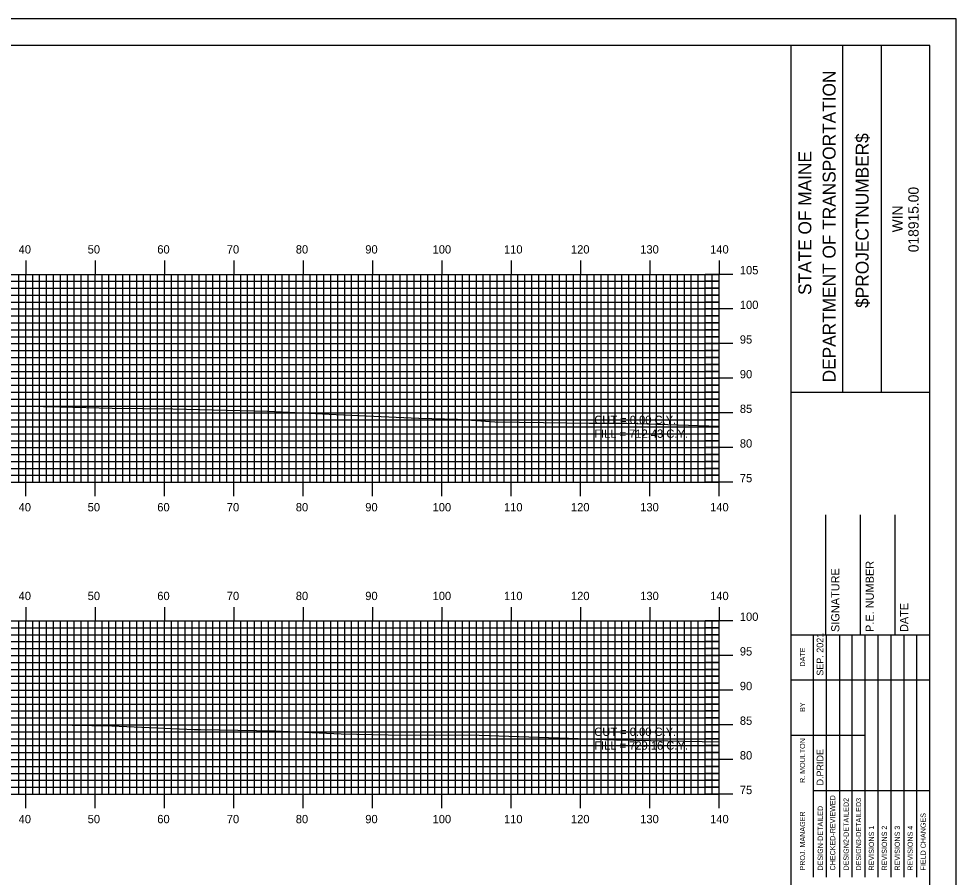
# Model space of a CAD drawing. Extents: x 854116 to 854460, y 364366 to 364586.
# Drawn here: x 854321.2 to 854456.4, y 364461.8 to 364585.7 of the extents above; entities that cross this region are included whole.
import ezdxf

# ---------------------------------------------------------------- set-up
doc = ezdxf.new("R2010")
doc.units = 0
for name, color, linetype in [('BORDER', 7, 'Continuous'), ('D_Text_Standard', 7, 'Continuous'), ('H_V ANNOTATION', 7, 'Continuous'), ('MAJOR', 7, 'Continuous'), ('MINOR', 7, 'Continuous'), ('PLOT BOUNDARY', 7, 'Continuous'), ('S_Roadway_Centerline', 7, 'Continuous')]:
    doc.layers.add(name, color=color, linetype=linetype)

msp = doc.modelspace()

# ---------------------------------------------------------------- linework, layer by layer
at = {"layer": 'BORDER'}
for p, q in [((854432.63, 364371.79), (854432.63, 364581.79)), ((854440.09, 364531.78), (854440.09, 364581.78)), ((854445.68, 364531.78), (854445.68, 364581.78)), ((854432.63, 364531.78), (854452.63, 364531.78)), ((854437.63, 364496.79), (854437.63, 364514.09)), ((854442.63, 364496.79), (854442.63, 364514.09)), ((854447.63, 364496.79), (854447.63, 364514.09)), ((854432.63, 364496.79), (854452.63, 364496.79))]:
    msp.add_line(p, q, dxfattribs=at)
msp.add_lwpolyline([(854132.63, 364371.79), (854452.63, 364371.79), (854452.63, 364581.79), (854132.63, 364581.79)], close=True, dxfattribs=at)
for points in [[(854435.86, 364490.29), (854435.86, 364496.79)], [(854437.73, 364461.8), (854437.73, 364496.79)], [(854439.59, 364496.79), (854439.59, 364461.8)], [(854441.45, 364461.8), (854441.45, 364496.79)], [(854443.32, 364461.8), (854443.32, 364496.79)], [(854445.18, 364461.8), (854445.18, 364496.79)], [(854447.04, 364461.8), (854447.04, 364496.79)], [(854448.91, 364461.8), (854448.91, 364496.79)], [(854450.77, 364461.8), (854450.77, 364496.79)], [(854435.86, 364461.8), (854435.86, 364495.38)], [(854432.63, 364490.29), (854452.63, 364490.29)], [(854432.63, 364482.29), (854435.86, 364482.29)], [(854435.86, 364482.29), (854443.31, 364482.29)], [(854435.86, 364474.29), (854452.63, 364474.29)]]:
    msp.add_lwpolyline(points, dxfattribs=at)
at = {"layer": 'MAJOR'}
for p, q in [((854322.23, 364550.79), (854322.23, 364548.79)), ((854332.23, 364550.79), (854332.23, 364548.79)), ((854342.23, 364550.79), (854342.23, 364548.79)), ((854352.23, 364550.79), (854352.23, 364548.79)), ((854362.23, 364550.79), (854362.23, 364548.79)), ((854372.23, 364550.79), (854372.23, 364548.79)), ((854382.23, 364550.79), (854382.23, 364548.79)), ((854392.23, 364550.79), (854392.23, 364548.79)), ((854402.23, 364550.79), (854402.23, 364548.79)), ((854412.23, 364550.79), (854412.23, 364548.79)), ((854422.23, 364550.79), (854422.23, 364548.79)), ((854142.23, 364548.79), (854422.23, 364548.79)), ((854142.23, 364548.79), (854422.23, 364548.79)), ((854322.23, 364518.79), (854322.23, 364548.79)), ((854332.23, 364518.79), (854332.23, 364548.79)), ((854342.23, 364518.79), (854342.23, 364548.79)), ((854352.23, 364518.79), (854352.23, 364548.79)), ((854362.23, 364518.79), (854362.23, 364548.79)), ((854372.23, 364518.79), (854372.23, 364548.79)), ((854382.23, 364518.79), (854382.23, 364548.79)), ((854392.23, 364518.79), (854392.23, 364548.79)), ((854402.23, 364518.79), (854402.23, 364548.79)), ((854412.23, 364518.79), (854412.23, 364548.79)), ((854424.23, 364548.79), (854420.23, 364548.79)), ((854422.23, 364518.79), (854422.23, 364548.79)), ((854422.23, 364518.79), (854422.23, 364548.79)), ((854142.23, 364543.79), (854422.23, 364543.79)), ((854424.23, 364543.79), (854420.23, 364543.79)), ((854142.23, 364538.79), (854422.23, 364538.79)), ((854424.23, 364538.79), (854420.23, 364538.79)), ((854142.23, 364533.79), (854422.23, 364533.79)), ((854424.23, 364533.79), (854420.23, 364533.79)), ((854142.23, 364528.79), (854422.23, 364528.79)), ((854424.23, 364528.79), (854420.23, 364528.79)), ((854142.23, 364523.79), (854422.23, 364523.79)), ((854424.23, 364523.79), (854420.23, 364523.79)), ((854142.23, 364518.79), (854422.23, 364518.79)), ((854142.23, 364518.79), (854422.23, 364518.79)), ((854322.23, 364516.78), (854322.23, 364518.79)), ((854332.23, 364516.78), (854332.23, 364518.79)), ((854342.23, 364516.78), (854342.23, 364518.79)), ((854352.23, 364516.78), (854352.23, 364518.79)), ((854362.23, 364516.78), (854362.23, 364518.79)), ((854372.23, 364516.78), (854372.23, 364518.79)), ((854382.23, 364516.78), (854382.23, 364518.79)), ((854392.23, 364516.78), (854392.23, 364518.79)), ((854402.23, 364516.78), (854402.23, 364518.79)), ((854412.23, 364516.78), (854412.23, 364518.79)), ((854424.23, 364518.79), (854420.23, 364518.79)), ((854422.23, 364516.78), (854422.23, 364518.79)), ((854322.23, 364500.79), (854322.23, 364498.79)), ((854332.23, 364500.79), (854332.23, 364498.79)), ((854342.23, 364500.79), (854342.23, 364498.79)), ((854352.23, 364500.79), (854352.23, 364498.79)), ((854362.23, 364500.79), (854362.23, 364498.79)), ((854372.23, 364500.79), (854372.23, 364498.79)), ((854382.23, 364500.79), (854382.23, 364498.79)), ((854392.23, 364500.79), (854392.23, 364498.79)), ((854402.23, 364500.79), (854402.23, 364498.79)), ((854412.23, 364500.79), (854412.23, 364498.79)), ((854422.23, 364500.79), (854422.23, 364498.79)), ((854142.23, 364498.79), (854422.23, 364498.79)), ((854142.23, 364498.79), (854422.23, 364498.79)), ((854322.23, 364473.79), (854322.23, 364498.79)), ((854332.23, 364473.79), (854332.23, 364498.79)), ((854342.23, 364473.79), (854342.23, 364498.79)), ((854352.23, 364473.79), (854352.23, 364498.79)), ((854362.23, 364473.79), (854362.23, 364498.79)), ((854372.23, 364473.79), (854372.23, 364498.79)), ((854382.23, 364473.79), (854382.23, 364498.79)), ((854392.23, 364473.79), (854392.23, 364498.79)), ((854402.23, 364473.79), (854402.23, 364498.79)), ((854412.23, 364473.79), (854412.23, 364498.79)), ((854424.23, 364498.79), (854420.23, 364498.79)), ((854422.23, 364473.79), (854422.23, 364498.79)), ((854422.23, 364473.79), (854422.23, 364498.79)), ((854142.23, 364493.79), (854422.23, 364493.79)), ((854424.23, 364493.79), (854420.23, 364493.79)), ((854142.23, 364488.79), (854422.23, 364488.79)), ((854424.23, 364488.79), (854420.23, 364488.79)), ((854142.23, 364483.79), (854422.23, 364483.79)), ((854424.23, 364483.79), (854420.23, 364483.79)), ((854142.23, 364478.79), (854422.23, 364478.79)), ((854424.23, 364478.79), (854420.23, 364478.79)), ((854142.23, 364473.79), (854422.23, 364473.79)), ((854142.23, 364473.79), (854422.23, 364473.79)), ((854322.23, 364471.78), (854322.23, 364473.79)), ((854332.23, 364471.78), (854332.23, 364473.79)), ((854342.23, 364471.78), (854342.23, 364473.79)), ((854352.23, 364471.78), (854352.23, 364473.79)), ((854362.23, 364471.78), (854362.23, 364473.79)), ((854372.23, 364471.78), (854372.23, 364473.79)), ((854382.23, 364471.78), (854382.23, 364473.79)), ((854392.23, 364471.78), (854392.23, 364473.79)), ((854402.23, 364471.78), (854402.23, 364473.79)), ((854412.23, 364471.78), (854412.23, 364473.79)), ((854424.23, 364473.79), (854420.23, 364473.79)), ((854422.23, 364471.78), (854422.23, 364473.79))]:
    msp.add_line(p, q, dxfattribs=at)
at = {"layer": 'MINOR'}
for p, q in [((854142.23, 364547.79), (854422.23, 364547.79)), ((854321.23, 364518.79), (854321.23, 364548.79)), ((854323.23, 364518.79), (854323.23, 364548.79)), ((854324.23, 364518.79), (854324.23, 364548.79)), ((854325.23, 364518.79), (854325.23, 364548.79)), ((854326.23, 364518.79), (854326.23, 364548.79)), ((854327.23, 364518.79), (854327.23, 364548.79)), ((854328.23, 364518.79), (854328.23, 364548.79)), ((854329.23, 364518.79), (854329.23, 364548.79)), ((854330.23, 364518.79), (854330.23, 364548.79)), ((854331.23, 364518.79), (854331.23, 364548.79)), ((854333.23, 364518.79), (854333.23, 364548.79)), ((854334.23, 364518.79), (854334.23, 364548.79)), ((854335.23, 364518.79), (854335.23, 364548.79)), ((854336.23, 364518.79), (854336.23, 364548.79)), ((854337.23, 364518.79), (854337.23, 364548.79)), ((854338.23, 364518.79), (854338.23, 364548.79)), ((854339.23, 364518.79), (854339.23, 364548.79)), ((854340.23, 364518.79), (854340.23, 364548.79)), ((854341.23, 364518.79), (854341.23, 364548.79)), ((854343.23, 364518.79), (854343.23, 364548.79)), ((854344.23, 364518.79), (854344.23, 364548.79)), ((854345.23, 364518.79), (854345.23, 364548.79)), ((854346.23, 364518.79), (854346.23, 364548.79)), ((854347.23, 364518.79), (854347.23, 364548.79)), ((854348.23, 364518.79), (854348.23, 364548.79)), ((854349.23, 364518.79), (854349.23, 364548.79)), ((854350.23, 364518.79), (854350.23, 364548.79)), ((854351.23, 364518.79), (854351.23, 364548.79)), ((854353.23, 364518.79), (854353.23, 364548.79)), ((854354.23, 364518.79), (854354.23, 364548.79)), ((854355.23, 364518.79), (854355.23, 364548.79)), ((854356.23, 364518.79), (854356.23, 364548.79)), ((854357.23, 364518.79), (854357.23, 364548.79)), ((854358.23, 364518.79), (854358.23, 364548.79)), ((854359.23, 364518.79), (854359.23, 364548.79)), ((854360.23, 364518.79), (854360.23, 364548.79)), ((854361.23, 364518.79), (854361.23, 364548.79)), ((854363.23, 364518.79), (854363.23, 364548.79)), ((854364.23, 364518.79), (854364.23, 364548.79)), ((854365.23, 364518.79), (854365.23, 364548.79)), ((854366.23, 364518.79), (854366.23, 364548.79)), ((854367.23, 364518.79), (854367.23, 364548.79)), ((854368.23, 364518.79), (854368.23, 364548.79)), ((854369.23, 364518.79), (854369.23, 364548.79)), ((854370.23, 364518.79), (854370.23, 364548.79)), ((854371.23, 364518.79), (854371.23, 364548.79)), ((854373.23, 364518.79), (854373.23, 364548.79)), ((854374.23, 364518.79), (854374.23, 364548.79)), ((854375.23, 364518.79), (854375.23, 364548.79)), ((854376.23, 364518.79), (854376.23, 364548.79)), ((854377.23, 364518.79), (854377.23, 364548.79)), ((854378.23, 364518.79), (854378.23, 364548.79)), ((854379.23, 364518.79), (854379.23, 364548.79)), ((854380.23, 364518.79), (854380.23, 364548.79)), ((854381.23, 364518.79), (854381.23, 364548.79)), ((854383.23, 364518.79), (854383.23, 364548.79)), ((854384.23, 364518.79), (854384.23, 364548.79)), ((854385.23, 364518.79), (854385.23, 364548.79)), ((854386.23, 364518.79), (854386.23, 364548.79)), ((854387.23, 364518.79), (854387.23, 364548.79)), ((854388.23, 364518.79), (854388.23, 364548.79)), ((854389.23, 364518.79), (854389.23, 364548.79)), ((854390.23, 364518.79), (854390.23, 364548.79)), ((854391.23, 364518.79), (854391.23, 364548.79)), ((854393.23, 364518.79), (854393.23, 364548.79)), ((854394.23, 364518.79), (854394.23, 364548.79)), ((854395.23, 364518.79), (854395.23, 364548.79)), ((854396.23, 364518.79), (854396.23, 364548.79)), ((854397.23, 364518.79), (854397.23, 364548.79)), ((854398.23, 364518.79), (854398.23, 364548.79)), ((854399.23, 364518.79), (854399.23, 364548.79)), ((854400.23, 364518.79), (854400.23, 364548.79)), ((854401.23, 364518.79), (854401.23, 364548.79)), ((854403.23, 364518.79), (854403.23, 364548.79)), ((854404.23, 364518.79), (854404.23, 364548.79)), ((854405.23, 364518.79), (854405.23, 364548.79)), ((854406.23, 364518.79), (854406.23, 364548.79)), ((854407.23, 364518.79), (854407.23, 364548.79)), ((854408.23, 364518.79), (854408.23, 364548.79)), ((854409.23, 364518.79), (854409.23, 364548.79)), ((854410.23, 364518.79), (854410.23, 364548.79)), ((854411.23, 364518.79), (854411.23, 364548.79)), ((854413.23, 364518.79), (854413.23, 364548.79)), ((854414.23, 364518.79), (854414.23, 364548.79)), ((854415.23, 364518.79), (854415.23, 364548.79)), ((854416.23, 364518.79), (854416.23, 364548.79)), ((854417.23, 364518.79), (854417.23, 364548.79)), ((854418.23, 364518.79), (854418.23, 364548.79)), ((854419.23, 364518.79), (854419.23, 364548.79)), ((854420.23, 364518.79), (854420.23, 364548.79)), ((854422.23, 364547.79), (854420.23, 364547.79)), ((854421.23, 364518.79), (854421.23, 364548.79)), ((854142.23, 364546.79), (854422.23, 364546.79)), ((854422.23, 364546.79), (854420.23, 364546.79)), ((854142.23, 364545.79), (854422.23, 364545.79)), ((854422.23, 364545.79), (854420.23, 364545.79)), ((854142.23, 364544.79), (854422.23, 364544.79)), ((854422.23, 364544.79), (854420.23, 364544.79)), ((854142.23, 364542.79), (854422.23, 364542.79)), ((854422.23, 364542.79), (854420.23, 364542.79)), ((854142.23, 364541.79), (854422.23, 364541.79)), ((854422.23, 364541.79), (854420.23, 364541.79)), ((854142.23, 364540.79), (854422.23, 364540.79)), ((854142.23, 364539.79), (854422.23, 364539.79)), ((854422.23, 364540.79), (854420.23, 364540.79)), ((854422.23, 364539.79), (854420.23, 364539.79)), ((854142.23, 364537.79), (854422.23, 364537.79)), ((854422.23, 364537.79), (854420.23, 364537.79)), ((854142.23, 364536.79), (854422.23, 364536.79)), ((854142.23, 364535.79), (854422.23, 364535.79)), ((854422.23, 364536.79), (854420.23, 364536.79)), ((854422.23, 364535.79), (854420.23, 364535.79)), ((854142.23, 364534.79), (854422.23, 364534.79)), ((854422.23, 364534.79), (854420.23, 364534.79)), ((854142.23, 364532.79), (854422.23, 364532.79)), ((854422.23, 364532.79), (854420.23, 364532.79)), ((854142.23, 364531.79), (854422.23, 364531.79)), ((854422.23, 364531.79), (854420.23, 364531.79)), ((854142.23, 364530.79), (854422.23, 364530.79)), ((854422.23, 364530.79), (854420.23, 364530.79)), ((854142.23, 364529.79), (854422.23, 364529.79)), ((854422.23, 364529.79), (854420.23, 364529.79)), ((854142.23, 364527.79), (854422.23, 364527.79)), ((854422.23, 364527.79), (854420.23, 364527.79)), ((854142.23, 364526.79), (854422.23, 364526.79)), ((854422.23, 364526.79), (854420.23, 364526.79)), ((854142.23, 364525.79), (854422.23, 364525.79)), ((854142.23, 364524.79), (854422.23, 364524.79)), ((854422.23, 364525.79), (854420.23, 364525.79)), ((854422.23, 364524.79), (854420.23, 364524.79)), ((854142.23, 364522.79), (854422.23, 364522.79)), ((854422.23, 364522.79), (854420.23, 364522.79)), ((854142.23, 364521.79), (854422.23, 364521.79)), ((854142.23, 364520.79), (854422.23, 364520.79)), ((854422.23, 364521.79), (854420.23, 364521.79)), ((854422.23, 364520.79), (854420.23, 364520.79)), ((854142.23, 364519.79), (854422.23, 364519.79)), ((854422.23, 364519.79), (854420.23, 364519.79)), ((854142.23, 364497.79), (854422.23, 364497.79)), ((854321.23, 364473.79), (854321.23, 364498.79)), ((854323.23, 364473.79), (854323.23, 364498.79)), ((854324.23, 364473.79), (854324.23, 364498.79)), ((854325.23, 364473.79), (854325.23, 364498.79)), ((854326.23, 364473.79), (854326.23, 364498.79)), ((854327.23, 364473.79), (854327.23, 364498.79)), ((854328.23, 364473.79), (854328.23, 364498.79)), ((854329.23, 364473.79), (854329.23, 364498.79)), ((854330.23, 364473.79), (854330.23, 364498.79)), ((854331.23, 364473.79), (854331.23, 364498.79)), ((854333.23, 364473.79), (854333.23, 364498.79)), ((854334.23, 364473.79), (854334.23, 364498.79)), ((854335.23, 364473.79), (854335.23, 364498.79)), ((854336.23, 364473.79), (854336.23, 364498.79)), ((854337.23, 364473.79), (854337.23, 364498.79)), ((854338.23, 364473.79), (854338.23, 364498.79)), ((854339.23, 364473.79), (854339.23, 364498.79)), ((854340.23, 364473.79), (854340.23, 364498.79)), ((854341.23, 364473.79), (854341.23, 364498.79)), ((854343.23, 364473.79), (854343.23, 364498.79)), ((854344.23, 364473.79), (854344.23, 364498.79)), ((854345.23, 364473.79), (854345.23, 364498.79)), ((854346.23, 364473.79), (854346.23, 364498.79)), ((854347.23, 364473.79), (854347.23, 364498.79)), ((854348.23, 364473.79), (854348.23, 364498.79)), ((854349.23, 364473.79), (854349.23, 364498.79)), ((854350.23, 364473.79), (854350.23, 364498.79)), ((854351.23, 364473.79), (854351.23, 364498.79)), ((854353.23, 364473.79), (854353.23, 364498.79)), ((854354.23, 364473.79), (854354.23, 364498.79)), ((854355.23, 364473.79), (854355.23, 364498.79)), ((854356.23, 364473.79), (854356.23, 364498.79)), ((854357.23, 364473.79), (854357.23, 364498.79)), ((854358.23, 364473.79), (854358.23, 364498.79)), ((854359.23, 364473.79), (854359.23, 364498.79)), ((854360.23, 364473.79), (854360.23, 364498.79)), ((854361.23, 364473.79), (854361.23, 364498.79)), ((854363.23, 364473.79), (854363.23, 364498.79)), ((854364.23, 364473.79), (854364.23, 364498.79)), ((854365.23, 364473.79), (854365.23, 364498.79)), ((854366.23, 364473.79), (854366.23, 364498.79)), ((854367.23, 364473.79), (854367.23, 364498.79)), ((854368.23, 364473.79), (854368.23, 364498.79)), ((854369.23, 364473.79), (854369.23, 364498.79)), ((854370.23, 364473.79), (854370.23, 364498.79)), ((854371.23, 364473.79), (854371.23, 364498.79)), ((854373.23, 364473.79), (854373.23, 364498.79)), ((854374.23, 364473.79), (854374.23, 364498.79)), ((854375.23, 364473.79), (854375.23, 364498.79)), ((854376.23, 364473.79), (854376.23, 364498.79)), ((854377.23, 364473.79), (854377.23, 364498.79)), ((854378.23, 364473.79), (854378.23, 364498.79)), ((854379.23, 364473.79), (854379.23, 364498.79)), ((854380.23, 364473.79), (854380.23, 364498.79)), ((854381.23, 364473.79), (854381.23, 364498.79)), ((854383.23, 364473.79), (854383.23, 364498.79)), ((854384.23, 364473.79), (854384.23, 364498.79)), ((854385.23, 364473.79), (854385.23, 364498.79)), ((854386.23, 364473.79), (854386.23, 364498.79)), ((854387.23, 364473.79), (854387.23, 364498.79)), ((854388.23, 364473.79), (854388.23, 364498.79)), ((854389.23, 364473.79), (854389.23, 364498.79)), ((854390.23, 364473.79), (854390.23, 364498.79)), ((854391.23, 364473.79), (854391.23, 364498.79)), ((854393.23, 364473.79), (854393.23, 364498.79)), ((854394.23, 364473.79), (854394.23, 364498.79)), ((854395.23, 364473.79), (854395.23, 364498.79)), ((854396.23, 364473.79), (854396.23, 364498.79)), ((854397.23, 364473.79), (854397.23, 364498.79)), ((854398.23, 364473.79), (854398.23, 364498.79)), ((854399.23, 364473.79), (854399.23, 364498.79)), ((854400.23, 364473.79), (854400.23, 364498.79)), ((854401.23, 364473.79), (854401.23, 364498.79)), ((854403.23, 364473.79), (854403.23, 364498.79)), ((854404.23, 364473.79), (854404.23, 364498.79)), ((854405.23, 364473.79), (854405.23, 364498.79)), ((854406.23, 364473.79), (854406.23, 364498.79)), ((854407.23, 364473.79), (854407.23, 364498.79)), ((854408.23, 364473.79), (854408.23, 364498.79)), ((854409.23, 364473.79), (854409.23, 364498.79)), ((854410.23, 364473.79), (854410.23, 364498.79)), ((854411.23, 364473.79), (854411.23, 364498.79)), ((854413.23, 364473.79), (854413.23, 364498.79)), ((854414.23, 364473.79), (854414.23, 364498.79)), ((854415.23, 364473.79), (854415.23, 364498.79)), ((854416.23, 364473.79), (854416.23, 364498.79)), ((854417.23, 364473.79), (854417.23, 364498.79)), ((854418.23, 364473.79), (854418.23, 364498.79)), ((854419.23, 364473.79), (854419.23, 364498.79)), ((854420.23, 364473.79), (854420.23, 364498.79)), ((854422.23, 364497.79), (854420.23, 364497.79)), ((854421.23, 364473.79), (854421.23, 364498.79)), ((854142.23, 364496.79), (854422.23, 364496.79)), ((854422.23, 364496.79), (854420.23, 364496.79)), ((854142.23, 364495.79), (854422.23, 364495.79)), ((854422.23, 364495.79), (854420.23, 364495.79)), ((854142.23, 364494.79), (854422.23, 364494.79)), ((854422.23, 364494.79), (854420.23, 364494.79)), ((854142.23, 364492.79), (854422.23, 364492.79)), ((854422.23, 364492.79), (854420.23, 364492.79)), ((854142.23, 364491.79), (854422.23, 364491.79)), ((854422.23, 364491.79), (854420.23, 364491.79)), ((854142.23, 364490.79), (854422.23, 364490.79)), ((854142.23, 364489.79), (854422.23, 364489.79)), ((854422.23, 364490.79), (854420.23, 364490.79)), ((854422.23, 364489.79), (854420.23, 364489.79)), ((854142.23, 364487.79), (854422.23, 364487.79)), ((854142.23, 364486.79), (854422.23, 364486.79)), ((854422.23, 364487.79), (854420.23, 364487.79)), ((854422.23, 364486.79), (854420.23, 364486.79)), ((854142.23, 364485.79), (854422.23, 364485.79)), ((854422.23, 364485.79), (854420.23, 364485.79)), ((854142.23, 364484.79), (854422.23, 364484.79)), ((854422.23, 364484.79), (854420.23, 364484.79)), ((854142.23, 364482.79), (854422.23, 364482.79)), ((854422.23, 364482.79), (854420.23, 364482.79)), ((854142.23, 364481.79), (854422.23, 364481.79)), ((854422.23, 364481.79), (854420.23, 364481.79)), ((854142.23, 364480.79), (854422.23, 364480.79)), ((854422.23, 364480.79), (854420.23, 364480.79)), ((854142.23, 364479.79), (854422.23, 364479.79)), ((854422.23, 364479.79), (854420.23, 364479.79)), ((854142.23, 364477.79), (854422.23, 364477.79)), ((854422.23, 364477.79), (854420.23, 364477.79)), ((854142.23, 364476.79), (854422.23, 364476.79)), ((854422.23, 364476.79), (854420.23, 364476.79)), ((854142.23, 364475.79), (854422.23, 364475.79)), ((854142.23, 364474.79), (854422.23, 364474.79)), ((854422.23, 364475.79), (854420.23, 364475.79)), ((854422.23, 364474.79), (854420.23, 364474.79))]:
    msp.add_line(p, q, dxfattribs=at)
at = {"layer": 'PLOT BOUNDARY'}
msp.add_lwpolyline([(854116.44, 364365.67), (854456.44, 364365.67), (854456.44, 364585.67), (854116.44, 364585.67)], close=True, dxfattribs=at)
at = {"layer": 'S_Roadway_Centerline'}
for points in [[(854320.11, 364529.84), (854327.16, 364529.68), (854334.71, 364529.49), (854343.44, 364529.37), (854357.08, 364529.05), (854367.02, 364528.58), (854378.92, 364528.02), (854384.49, 364527.88), (854389.89, 364527.52), (854396.92, 364527.42), (854403.51, 364527.33), (854408.94, 364527.31), (854422.23, 364526.86)], [(854318.1, 364483.75), (854326.02, 364483.77), (854334.65, 364483.66), (854346.52, 364483.13), (854347.45, 364483.1), (854358.19, 364482.9), (854367.74, 364482.47), (854374.49, 364482.35), (854387.63, 364482.28), (854403.37, 364481.76), (854405.77, 364481.66), (854407.44, 364481.62), (854422.23, 364481.34)]]:
    msp.add_lwpolyline(points, dxfattribs=at)

# ---------------------------------------------------------------- texts
at = {"layer": 'BORDER'}
for s, height, p in [('DEPARTMENT OF TRANSPORTATION', 1.8635, (854439.04, 364533.2)), ('$PROJECTNUMBER$', 1.8635, (854443.81, 364543.95)), ('STATE OF MAINE', 1.8635, (854435.54, 364545.81)), ('018915.00', 1.491, (854451.02, 364551.98)), ('WIN', 1.491, (854448.7, 364554.85)), ('P.E. NUMBER', 1.1811, (854444.55, 364497.18)), ('SIGNATURE', 1.181, (854439.59, 364497.18)), ('DATE', 1.181, (854449.51, 364497.18)), ('SEP. 2021', 0.969, (854437.28, 364490.88)), ('DATE', 0.743, (854434.64, 364492.2)), ('BY', 0.743, (854434.64, 364485.66)), ('R. MOULTON', 0.745, (854434.64, 364475.4)), ('D.PRIDE', 0.969, (854437.28, 364475.04)), ('CHECKED-REVIEWED', 0.7455, (854438.99, 364462.77)), ('DESIGN2-DETAILED2', 0.7455, (854440.93, 364462.77)), ('DESIGN3-DETAILED3', 0.7455, (854442.72, 364462.77)), ('PROJ. MANAGER', 0.7455, (854434.64, 364462.77)), ('DESIGN-DETAILED', 0.7455, (854437.2, 364462.77)), ('FIELD CHANGES', 0.7455, (854452.04, 364462.77)), ('REVISIONS 1', 0.7455, (854444.58, 364462.77)), ('REVISIONS 2', 0.7455, (854446.45, 364462.77)), ('REVISIONS 3', 0.7455, (854448.31, 364462.77)), ('REVISIONS 4', 0.7455, (854450.17, 364462.77))]:
    msp.add_text(s, height=height, rotation=90, dxfattribs=at).set_placement(p)
at = {"layer": 'D_Text_Standard'}
for s, p in [('CUT = 0.00 C.Y.', (854404.23, 364527.19)), ('FILL = 712.43 C.Y.', (854404.23, 364525.2)), ('CUT = 0.00 C.Y.', (854404.23, 364482.19)), ('FILL = 729.16 C.Y.', (854404.23, 364480.2))]:
    msp.add_text(s, height=1.2, dxfattribs=at).set_placement(p)
at = {"layer": 'H_V ANNOTATION'}
for s, p in [('40', (854321.2, 364551.79)), ('50', (854331.16, 364551.79)), ('60', (854341.2, 364551.79)), ('70', (854351.23, 364551.79)), ('80', (854361.18, 364551.79)), ('90', (854371.2, 364551.79)), ('100', (854380.91, 364551.79)), ('110', (854391.21, 364551.79)), ('120', (854400.87, 364551.79)), ('130', (854410.86, 364551.79)), ('140', (854420.94, 364551.79)), ('105', (854425.23, 364548.79)), ('100', (854425.23, 364543.79)), ('95', (854425.23, 364538.79)), ('90', (854425.23, 364533.79)), ('85', (854425.23, 364528.79)), ('80', (854425.23, 364523.79)), ('75', (854425.23, 364518.79)), ('40', (854321.2, 364514.59)), ('50', (854331.16, 364514.59)), ('60', (854341.2, 364514.59)), ('70', (854351.23, 364514.59)), ('80', (854361.18, 364514.59)), ('90', (854371.2, 364514.59)), ('100', (854380.91, 364514.59)), ('110', (854391.21, 364514.59)), ('120', (854400.87, 364514.59)), ('130', (854410.86, 364514.59)), ('140', (854420.94, 364514.59)), ('40', (854321.2, 364501.79)), ('50', (854331.16, 364501.79)), ('60', (854341.2, 364501.79)), ('70', (854351.23, 364501.79)), ('80', (854361.18, 364501.79)), ('90', (854371.2, 364501.79)), ('100', (854380.91, 364501.79)), ('110', (854391.21, 364501.79)), ('120', (854400.87, 364501.79)), ('130', (854410.86, 364501.79)), ('140', (854420.94, 364501.79)), ('100', (854425.23, 364498.79)), ('95', (854425.23, 364493.79)), ('90', (854425.23, 364488.79)), ('85', (854425.23, 364483.79)), ('80', (854425.23, 364478.79)), ('75', (854425.23, 364473.79)), ('40', (854321.2, 364469.59)), ('50', (854331.16, 364469.59)), ('60', (854341.2, 364469.59)), ('70', (854351.23, 364469.59)), ('80', (854361.18, 364469.59)), ('90', (854371.2, 364469.59)), ('100', (854380.91, 364469.59)), ('110', (854391.21, 364469.59)), ('120', (854400.87, 364469.59)), ('130', (854410.86, 364469.59)), ('140', (854420.94, 364469.59))]:
    msp.add_text(s, height=1.2, dxfattribs=at).set_placement(p)

doc.saveas('drawing.dxf')
